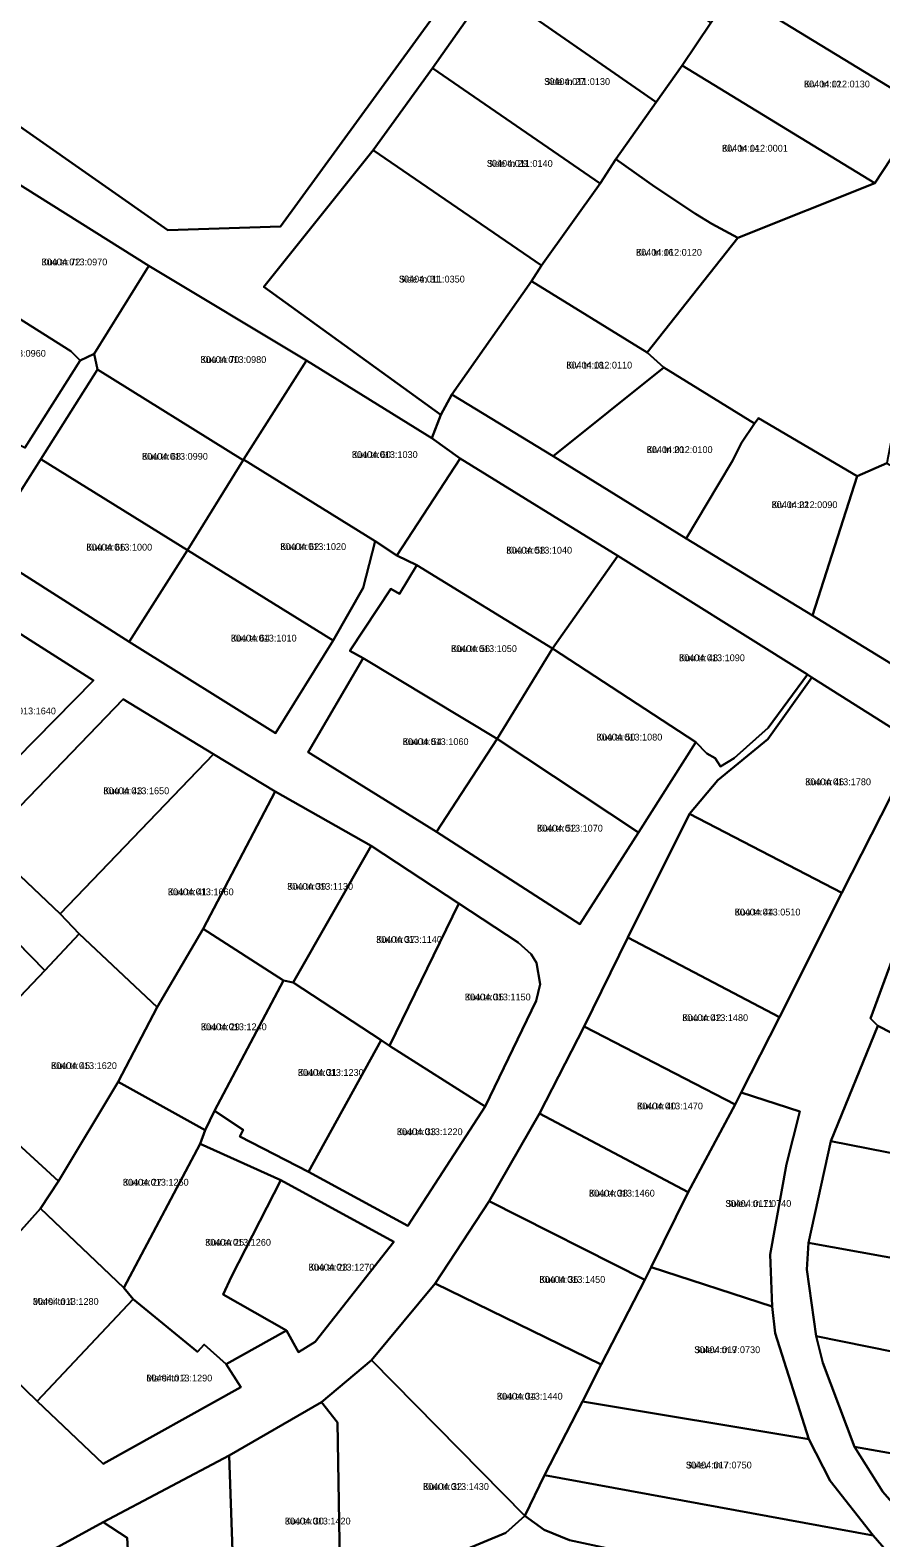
# Model space of a CAD drawing. Extents: x 542681 to 554572, y 6566489 to 6580482.
# Drawn here: x 543954 to 544141.3, y 6575830.3 to 6576162.5 of the extents above; entities that cross this region are included whole.
import ezdxf

# ---------------------------------------------------------------- set-up
doc = ezdxf.new("R2010")
doc.units = 0
for name, color, linetype in [('L_AADRESS', 7, 'Continuous'), ('PIIR', 7, 'Continuous'), ('TUNNUS', 7, 'Continuous')]:
    doc.layers.add(name, color=color, linetype=linetype)

msp = doc.modelspace()

# ---------------------------------------------------------------- linework, layer by layer
at = {"layer": 'PIIR'}
for points in [[(543939.43, 6576208.34), (543951.32, 6576196.79), (543973.39, 6576176.45), (543996.3, 6576200.53), (544043.16, 6576166.01), (544009.15, 6576119.22), (543984.31, 6576118.38), (543906.78, 6576172.72)], [(544067.39, 6576188.74), (544103.91, 6576164.12), (544097.55, 6576154.68), (544091.82, 6576146.63), (544055.21, 6576172.06)], [(544115.93, 6576181.35), (544120.28, 6576187.57), (544161.1, 6576161.82), (544150.9, 6576145.26), (544108.81, 6576170.96)], [(544055.21, 6576172.06), (544091.82, 6576146.63), (544082.95, 6576134.05), (544079.5, 6576128.73), (544042.61, 6576154.11)], [(544103.91, 6576164.12), (544108.81, 6576170.96), (544150.9, 6576145.26), (544139.99, 6576128.75), (544097.55, 6576154.68)], [(544097.55, 6576154.68), (544139.99, 6576128.75), (544109.84, 6576116.75), (544104.09, 6576119.83), (544100.51, 6576121.98), (544091.53, 6576127.99), (544082.95, 6576134.05), (544091.82, 6576146.63)], [(544042.61, 6576154.11), (544079.5, 6576128.73), (544066.63, 6576110.61), (544029.57, 6576136.02)], [(544029.57, 6576136.02), (544066.63, 6576110.61), (544064.43, 6576107.19), (544046.85, 6576082.24), (544044.41, 6576077.75), (544005.43, 6576105.91)], [(543980.11, 6576110.56), (543968.11, 6576091.17), (543964.98, 6576089.69), (543962.96, 6576091.73), (543933.01, 6576110.61), (543933.19, 6576111.32), (543946.49, 6576131.63)], [(544066.63, 6576110.61), (544079.5, 6576128.73), (544082.95, 6576134.05), (544091.53, 6576127.99), (544100.51, 6576121.98), (544104.09, 6576119.83), (544109.84, 6576116.75), (544089.87, 6576091.5), (544064.43, 6576107.19)], [(543920.19, 6576091.57), (543933.01, 6576110.61), (543962.96, 6576091.73), (543964.98, 6576089.69), (543952.86, 6576070.45), (543950.15, 6576071.84), (543947.68, 6576073.32), (543945.36, 6576074.84)], [(543968.11, 6576091.17), (543980.11, 6576110.56), (544014.82, 6576089.71), (544000.98, 6576067.89), (544000.9, 6576067.76), (543968.82, 6576087.73)], [(544064.43, 6576107.19), (544089.87, 6576091.5), (544093.54, 6576088.13), (544069.2, 6576068.66), (544046.85, 6576082.24)], [(544000.98, 6576067.89), (544014.82, 6576089.71), (544042.43, 6576072.57), (544048.67, 6576068.09), (544034.78, 6576046.75), (544030.01, 6576049.88)], [(544093.54, 6576088.13), (544113.49, 6576075.86), (544110.67, 6576071.57), (544108.66, 6576067.57), (544105.49, 6576062.32), (544098.43, 6576050.5), (544069.2, 6576068.66)], [(543968.82, 6576087.73), (544000.9, 6576067.76), (543988.63, 6576047.94), (543956.32, 6576067.94)], [(544105.49, 6576062.32), (544108.66, 6576067.57), (544110.67, 6576071.57), (544113.49, 6576075.86), (544114.41, 6576077.03), (544136.1, 6576064.24), (544126.25, 6576033.56), (544098.43, 6576050.5)], [(543943.74, 6576048.11), (543956.32, 6576067.94), (543988.63, 6576047.94), (543975.77, 6576027.72)], [(544000.9, 6576067.76), (544000.98, 6576067.89), (544030.01, 6576049.88), (544027.36, 6576039.62), (544020.7, 6576028.04), (543988.63, 6576047.94)], [(544069.01, 6576026.23), (544039.13, 6576044.61), (544034.78, 6576046.75), (544048.67, 6576068.09), (544083.4, 6576046.69)], [(544136.1, 6576064.24), (544142.67, 6576067.09), (544167.98, 6576053.1), (544150.34, 6576018.8), (544126.25, 6576033.56)], [(543975.77, 6576027.72), (543988.63, 6576047.94), (544020.7, 6576028.04), (544008, 6576007.64)], [(544083.4, 6576046.69), (544125.2, 6576020.55), (544116.54, 6576008.76), (544109.04, 6576002.12), (544106.03, 6576000.24), (544104.85, 6576002.13), (544102.98, 6576003.14), (544100.6, 6576005.61), (544069.01, 6576026.23)], [(544024.39, 6576025.72), (544024.58, 6576025.99), (544033.44, 6576039.42), (544035.34, 6576038.28), (544039.13, 6576044.61), (544069.01, 6576026.23), (544056.85, 6576006.35), (544027.34, 6576024.14)], [(543922.41, 6576003.9), (543948.95, 6576031.34), (543967.93, 6576019.18), (543938.16, 6575988.94)], [(544069.01, 6576026.23), (544100.6, 6576005.61), (544087.95, 6575985.75), (544056.85, 6576006.35)], [(544015.2, 6576003.43), (544027.34, 6576024.14), (544056.85, 6576006.35), (544043.49, 6575985.84)], [(544105.46, 6575997.25), (544116.43, 6576006.3), (544126.15, 6576019.88), (544144.61, 6576008.23), (544147.47, 6576005.67), (544147.93, 6576002.3), (544132.71, 6575972.4), (544099.16, 6575989.84)], [(543945.84, 6575981.74), (543946.1, 6575985.66), (543974.47, 6576015.13), (543994.39, 6576003.01), (543960.64, 6575967.84)], [(544056.85, 6576006.35), (544087.95, 6575985.75), (544075.04, 6575965.51), (544043.49, 6575985.84)], [(543964.77, 6575963.44), (543960.64, 6575967.84), (543994.39, 6576003.01), (544007.99, 6575994.76), (543992.1, 6575964.51), (543981.94, 6575947.26)], [(544011.94, 6575952.7), (544009.8, 6575953.09), (543992.1, 6575964.51), (544007.99, 6575994.76), (544029.12, 6575982.79)], [(544099.16, 6575989.84), (544132.71, 6575972.4), (544119.04, 6575945.05), (544085.61, 6575962.56)], [(544029.12, 6575982.79), (544048.42, 6575970.12), (544033.12, 6575938.75), (544031.32, 6575939.97), (544011.94, 6575952.7)], [(543925.71, 6575941.32), (543916.27, 6575950.88), (543938.64, 6575974.25), (543957.22, 6575955.33), (543935.26, 6575932.29)], [(544048.42, 6575970.12), (544061.47, 6575961.49), (544064.31, 6575958.92), (544065.47, 6575957.05), (544066.33, 6575952.28), (544065.46, 6575948.67), (544054.23, 6575925.37), (544033.12, 6575938.75)], [(544139.03, 6575944.72), (544146.98, 6575966.27), (544188.06, 6575942.5), (544186.73, 6575939.59), (544177.98, 6575924.04), (544140.69, 6575943.15)], [(543935.26, 6575932.29), (543957.22, 6575955.33), (543964.77, 6575963.44), (543981.94, 6575947.26), (543973.38, 6575930.78), (543960.23, 6575908.93), (543942.27, 6575925.34)], [(543981.94, 6575947.26), (543992.1, 6575964.51), (544009.8, 6575953.09), (543994.58, 6575924.43), (543992.54, 6575920.17), (543973.38, 6575930.78)], [(544085.61, 6575962.56), (544119.04, 6575945.05), (544110.57, 6575928.47), (544109.24, 6575925.81), (544076.01, 6575942.98)], [(544000.94, 6575920.22), (543994.58, 6575924.43), (544009.8, 6575953.09), (544011.94, 6575952.7), (544031.32, 6575939.97), (544015.26, 6575911.01), (544000.15, 6575918.75)], [(544109.24, 6575925.81), (544098.93, 6575906.48), (544066.18, 6575923.86), (544076.01, 6575942.98)], [(544140.69, 6575943.15), (544177.98, 6575924.04), (544176.53, 6575920.81), (544175.57, 6575908.81), (544130.3, 6575917.75)], [(544033.12, 6575938.75), (544054.23, 6575925.37), (544037.17, 6575899.08), (544015.26, 6575911.01), (544031.32, 6575939.97)], [(543991.42, 6575917.13), (543974.62, 6575885.44), (543956.27, 6575902.9), (543960.23, 6575908.93), (543973.38, 6575930.78), (543992.54, 6575920.17)], [(543915.9, 6575898.68), (543942.27, 6575925.34), (543960.23, 6575908.93), (543956.27, 6575902.9), (543949, 6575894.77), (543945.94, 6575897.25), (543932.12, 6575883.17)], [(544098.93, 6575906.48), (544109.24, 6575925.81), (544110.57, 6575928.47), (544123.51, 6575924.24), (544120.54, 6575912.67), (544116.94, 6575892.79), (544117.42, 6575881.34), (544090.72, 6575889.96)], [(544089.33, 6575887.18), (544055.07, 6575904.52), (544066.18, 6575923.86), (544098.93, 6575906.48), (544090.72, 6575889.96)], [(543991.42, 6575917.13), (544009.17, 6575909.11), (543998.31, 6575887.93), (543996.5, 6575883.93), (544010.44, 6575876.02), (543997.19, 6575868.61), (543992.33, 6575872.95), (543990.84, 6575871.31), (543976.68, 6575882.94), (543974.62, 6575885.44)], [(544130.3, 6575917.75), (544175.57, 6575908.81), (544174.74, 6575900.64), (544176.16, 6575886.17), (544125.43, 6575895.3)], [(544010.44, 6575876.02), (543996.5, 6575883.93), (543998.31, 6575887.93), (544009.17, 6575909.11), (544034.09, 6575895.57), (544016.78, 6575873.56), (544013.06, 6575871.28)], [(543945.94, 6575897.25), (543949, 6575894.77), (543956.27, 6575902.9), (543974.62, 6575885.44), (543976.68, 6575882.94), (543955.54, 6575860.45), (543932.12, 6575883.17)], [(544043.2, 6575886.38), (544055.07, 6575904.52), (544089.33, 6575887.18), (544079.77, 6575868.52)], [(544125.04, 6575889.43), (544125.43, 6575895.3), (544176.16, 6575886.17), (544177.75, 6575876.67), (544178.16, 6575864.4), (544127.11, 6575874.75)], [(544117.42, 6575881.34), (544118.06, 6575875.43), (544125.51, 6575852.12), (544075.62, 6575860.39), (544079.77, 6575868.52), (544089.33, 6575887.18), (544090.72, 6575889.96)], [(544062.9, 6575835.19), (544029.14, 6575869.47), (544043.2, 6575886.38), (544079.77, 6575868.52), (544075.62, 6575860.39), (544067.27, 6575844.15)], [(543955.54, 6575860.45), (543976.68, 6575882.94), (543990.84, 6575871.31), (543992.33, 6575872.95), (543997.19, 6575868.61), (544000.39, 6575863.51), (543970.07, 6575846.66)], [(544128.58, 6575868.91), (544127.11, 6575874.75), (544178.16, 6575864.4), (544180.88, 6575847.95), (544181.25, 6575842.29), (544135.53, 6575850.42)], [(544022.32, 6575816.32), (544021.69, 6575855.76), (544018.14, 6575860.26), (544029.14, 6575869.47), (544062.9, 6575835.19), (544058.73, 6575831.44)], [(543997.82, 6575848.48), (544018.14, 6575860.26), (544021.69, 6575855.76), (544022.32, 6575816.32), (543999.3, 6575806.31)], [(544075.62, 6575860.39), (544125.51, 6575852.12), (544130.14, 6575842.89), (544139.64, 6575830.88), (544067.27, 6575844.15)], [(544141.79, 6575840.51), (544135.53, 6575850.42), (544181.25, 6575842.29), (544182.58, 6575802.43), (544177.26, 6575800.27), (544155.07, 6575825.29)], [(543975.35, 6575830.32), (543970.09, 6575833.78), (543997.82, 6575848.48), (543999.3, 6575806.31), (543977.3, 6575797.27)], [(544067.19, 6575832.08), (544062.9, 6575835.19), (544067.27, 6575844.15), (544139.64, 6575830.88), (544152.48, 6575816.01), (544125.07, 6575812.74), (544122.99, 6575815.81), (544121.31, 6575818.18), (544112.83, 6575821.25), (544072.74, 6575829.86)], [(543952.21, 6575816.43), (543951.46, 6575818.75), (543948.47, 6575821.95), (543970.09, 6575833.78), (543975.35, 6575830.32), (543977.3, 6575797.27), (543955.35, 6575783.8)]]:
    msp.add_lwpolyline(points, close=True, dxfattribs=at)
for points in [[(544177.97, 6576177.9), (544167.75, 6576160.33), (544157.66, 6576143.26), (544146.79, 6576125.53), (544146.54, 6576125.22), (544147.81, 6576101.4), (544149.06, 6576100.33), (544142.67, 6576067.09), (544136.1, 6576064.24), (544114.41, 6576077.03), (544113.49, 6576075.86), (544093.54, 6576088.13), (544089.87, 6576091.5), (544109.84, 6576116.75), (544139.99, 6576128.75), (544150.9, 6576145.26), (544161.1, 6576161.82), (544161.88, 6576161.84), (544172.2, 6576179.15)], [(543906.78, 6576172.72), (543984.31, 6576118.38), (544009.15, 6576119.22), (544043.16, 6576166.01)], [(544055.21, 6576172.06), (544042.61, 6576154.11), (544029.57, 6576136.02), (544005.43, 6576105.91), (544044.41, 6576077.75), (544042.43, 6576072.57), (544014.82, 6576089.71), (543980.11, 6576110.56), (543946.49, 6576131.63)], [(543952.86, 6576070.45), (543964.98, 6576089.69), (543968.11, 6576091.17), (543968.82, 6576087.73), (543956.32, 6576067.94), (543943.74, 6576048.11), (543975.77, 6576027.72), (544008, 6576007.64), (544020.7, 6576028.04), (544027.36, 6576039.62), (544030.01, 6576049.88), (544034.78, 6576046.75), (544039.13, 6576044.61), (544035.34, 6576038.28), (544033.44, 6576039.42), (544024.58, 6576025.99), (544024.39, 6576025.72), (544027.34, 6576024.14), (544015.2, 6576003.43), (544043.49, 6575985.84), (544075.04, 6575965.51), (544087.95, 6575985.75), (544100.6, 6576005.61), (544102.98, 6576003.14), (544104.85, 6576002.13), (544106.03, 6576000.24), (544109.04, 6576002.12), (544116.54, 6576008.76), (544125.2, 6576020.55), (544126.15, 6576019.88), (544116.43, 6576006.3), (544105.46, 6575997.25), (544099.16, 6575989.84), (544085.61, 6575962.56), (544076.01, 6575942.98), (544066.18, 6575923.86), (544055.07, 6575904.52), (544043.2, 6575886.38), (544029.14, 6575869.47), (544018.14, 6575860.26), (543997.82, 6575848.48), (543970.09, 6575833.78), (543948.47, 6575821.95)], [(544144.61, 6576008.23), (544126.15, 6576019.88), (544125.2, 6576020.55), (544083.4, 6576046.69), (544048.67, 6576068.09), (544042.43, 6576072.57), (544044.41, 6576077.75), (544046.85, 6576082.24), (544069.2, 6576068.66), (544098.43, 6576050.5), (544126.25, 6576033.56), (544150.34, 6576018.8)], [(543938.16, 6575988.94), (543967.93, 6576019.18), (543948.95, 6576031.34)], [(543932.12, 6575883.17), (543955.54, 6575860.45), (543970.07, 6575846.66), (544000.39, 6575863.51), (543997.19, 6575868.61), (544010.44, 6575876.02), (544013.06, 6575871.28), (544016.78, 6575873.56), (544034.09, 6575895.57), (544009.17, 6575909.11), (543991.42, 6575917.13), (543992.54, 6575920.17), (543994.58, 6575924.43), (544000.94, 6575920.22), (544000.15, 6575918.75), (544015.26, 6575911.01), (544037.17, 6575899.08), (544054.23, 6575925.37), (544065.46, 6575948.67), (544066.33, 6575952.28), (544065.47, 6575957.05), (544064.31, 6575958.92), (544061.47, 6575961.49), (544048.42, 6575970.12), (544029.12, 6575982.79), (544007.99, 6575994.76), (543994.39, 6576003.01), (543974.47, 6576015.13), (543946.1, 6575985.66)], [(544152.48, 6575816.01), (544139.64, 6575830.88), (544130.14, 6575842.89), (544125.51, 6575852.12), (544118.06, 6575875.43), (544117.42, 6575881.34), (544116.94, 6575892.79), (544120.54, 6575912.67), (544123.51, 6575924.24), (544110.57, 6575928.47), (544119.04, 6575945.05), (544132.71, 6575972.4), (544147.93, 6576002.3)], [(544209.01, 6575796.68), (544219.68, 6575834.73), (544224.92, 6575853.69), (544229.59, 6575870.78), (544233.34, 6575884.68), (544238.44, 6575902.3), (544247.19, 6575932.44), (544245.8, 6575934.54), (544226.63, 6575946.16), (544199.95, 6575962.06), (544198.79, 6575959.82), (544153.86, 6575985.85), (544146.98, 6575966.27), (544139.03, 6575944.72), (544140.69, 6575943.15), (544130.3, 6575917.75), (544125.43, 6575895.3), (544125.04, 6575889.43), (544127.11, 6575874.75), (544128.58, 6575868.91), (544135.53, 6575850.42), (544141.79, 6575840.51), (544155.07, 6575825.29)], [(543945.84, 6575981.74), (543960.64, 6575967.84), (543964.77, 6575963.44), (543957.22, 6575955.33), (543938.64, 6575974.25)], [(543929, 6575769.63), (543955.35, 6575783.8), (543977.3, 6575797.27), (543999.3, 6575806.31), (544022.32, 6575816.32), (544058.73, 6575831.44), (544062.9, 6575835.19), (544067.19, 6575832.08), (544072.74, 6575829.86), (544112.83, 6575821.25), (544121.31, 6575818.18), (544122.99, 6575815.81), (544125.07, 6575812.74), (544148.38, 6575778.69), (544179.3, 6575731.35), (544185.74, 6575722.2), (544198.53, 6575706), (544212.11, 6575690.23), (544215.51, 6575674.61), (544215.6, 6575636.7)]]:
    msp.add_lwpolyline(points, dxfattribs=at)

# ---------------------------------------------------------------- texts
at = {"layer": 'L_AADRESS'}
for s, p in [('Side tn 27', (544067.2, 6576150.4)), ('Kivi tn 12', (544124.41, 6576149.86)), ('Kivi tn 14', (544106.36, 6576135.71)), ('Side tn 29', (544054.57, 6576132.36)), ('Kuu tn 72', (543956.49, 6576110.66)), ('Kivi tn 16', (544087.43, 6576112.78)), ('Side tn 31', (544035.21, 6576106.88)), ('Kuu tn 70', (543991.5, 6576089.16)), ('Kivi tn 18', (544072.07, 6576087.93)), ('Kuu tn 68', (543978.63, 6576067.84)), ('Kuu tn 60', (544024.84, 6576068.23)), ('Kivi tn 20', (544089.78, 6576069.32)), ('Kivi tn 22', (544117.27, 6576057.19)), ('Kuu tn 66', (543966.37, 6576047.83)), ('Kuu tn 62', (544009.08, 6576047.96)), ('Kuu tn 58', (544058.84, 6576047.16)), ('Kuu tn 64', (543998.18, 6576027.79)), ('Kuu tn 56', (544046.69, 6576025.48)), ('Kuu tn 48', (544096.89, 6576023.46)), ('Kuu tn 54', (544036.04, 6576004.99)), ('Kuu tn 50', (544078.71, 6576005.99)), ('Kuu tn 43', (543970.12, 6575994.16)), ('Kuu tn 46', (544124.66, 6575996.14)), ('Kuu tn 52', (544065.61, 6575985.93)), ('Kuu tn 41', (543984.32, 6575971.9)), ('Kuu tn 39', (544010.61, 6575973.11)), ('Kuu tn 44', (544109.13, 6575967.45)), ('Kuu tn 37', (544030.18, 6575961.41)), ('Kuu tn 35', (544049.72, 6575948.74)), ('Kuu tn 42', (544097.6, 6575944.18)), ('Kuu tn 29', (543991.59, 6575942.17)), ('Kuu tn 45', (543958.6, 6575933.62)), ('Kuu tn 31', (544012.95, 6575932.11)), ('Kuu tn 40', (544087.65, 6575924.73)), ('Kuu tn 33', (544034.74, 6575919.06)), ('Kuu tn 27', (543974.41, 6575907.93)), ('Kuu tn 38', (544077.05, 6575905.52)), ('Sulevi tn 11', (544107.11, 6575903.25)), ('Kuu tn 25', (543992.53, 6575894.7)), ('Kuu tn 23', (544015.3, 6575889.22)), ('Kuu tn 36', (544066.14, 6575886.52)), ('Marsi tn 4', (543954.58, 6575881.67)), ('Sulevi tn 9', (544100.26, 6575871.04)), ('Marsi tn 2', (543979.6, 6575864.8)), ('Kuu tn 34', (544056.76, 6575860.79)), ('Sulevi tn 7', (544098.4, 6575845.63)), ('Kuu tn 32', (544040.52, 6575840.9)), ('Kuu tn 30', (544010.07, 6575833.29))]:
    msp.add_text(s, height=1.5, dxfattribs=at).set_placement(p)
at = {"layer": 'TUNNUS'}
for s, p in [('30404:011:0130', (544067.2, 6576150.4)), ('30404:012:0130', (544124.41, 6576149.86)), ('30404:012:0001', (544106.36, 6576135.71)), ('30404:011:0140', (544054.57, 6576132.36)), ('30404:013:0970', (543956.49, 6576110.66)), ('30404:012:0120', (544087.43, 6576112.78)), ('30404:011:0350', (544035.21, 6576106.88)), ('30404:013:0960', (543942.95, 6576090.53)), ('30404:013:0980', (543991.5, 6576089.16)), ('30404:012:0110', (544072.07, 6576087.93)), ('30404:013:0990', (543978.63, 6576067.84)), ('30404:013:1030', (544024.84, 6576068.23)), ('30404:012:0100', (544089.78, 6576069.32)), ('30404:012:0090', (544117.27, 6576057.19)), ('30404:013:1000', (543966.37, 6576047.83)), ('30404:013:1020', (544009.08, 6576047.96)), ('30404:013:1040', (544058.84, 6576047.16)), ('30404:013:1010', (543998.18, 6576027.79)), ('30404:013:1050', (544046.69, 6576025.48)), ('30404:013:1090', (544096.89, 6576023.46)), ('30404:013:1640', (543945.17, 6576011.75)), ('30404:013:1060', (544036.04, 6576004.99)), ('30404:013:1080', (544078.71, 6576005.99)), ('30404:013:1650', (543970.12, 6575994.16)), ('30404:013:1780', (544124.66, 6575996.14)), ('30404:013:1070', (544065.61, 6575985.93)), ('30404:013:1660', (543984.32, 6575971.9)), ('30404:013:1130', (544010.61, 6575973.11)), ('30404:013:0510', (544109.13, 6575967.45)), ('30404:013:1140', (544030.18, 6575961.41)), ('30404:013:1150', (544049.72, 6575948.74)), ('30404:013:1480', (544097.6, 6575944.18)), ('30404:013:1240', (543991.59, 6575942.17)), ('30404:013:1620', (543958.6, 6575933.62)), ('30404:013:1230', (544012.95, 6575932.11)), ('30404:013:1470', (544087.65, 6575924.73)), ('30404:013:1220', (544034.74, 6575919.06)), ('30404:013:1250', (543974.41, 6575907.93)), ('30404:013:1460', (544077.05, 6575905.52)), ('30404:017:0740', (544107.11, 6575903.25)), ('30404:013:1260', (543992.53, 6575894.7)), ('30404:013:1270', (544015.3, 6575889.22)), ('30404:013:1450', (544066.14, 6575886.52)), ('30404:013:1280', (543954.58, 6575881.67)), ('30404:017:0730', (544100.26, 6575871.04)), ('30404:013:1290', (543979.6, 6575864.8)), ('30404:013:1440', (544056.76, 6575860.79)), ('30404:017:0750', (544098.4, 6575845.63)), ('30404:013:1430', (544040.52, 6575840.9)), ('30404:013:1420', (544010.07, 6575833.29))]:
    msp.add_text(s, height=1.5, dxfattribs=at).set_placement(p)

doc.saveas('drawing.dxf')
